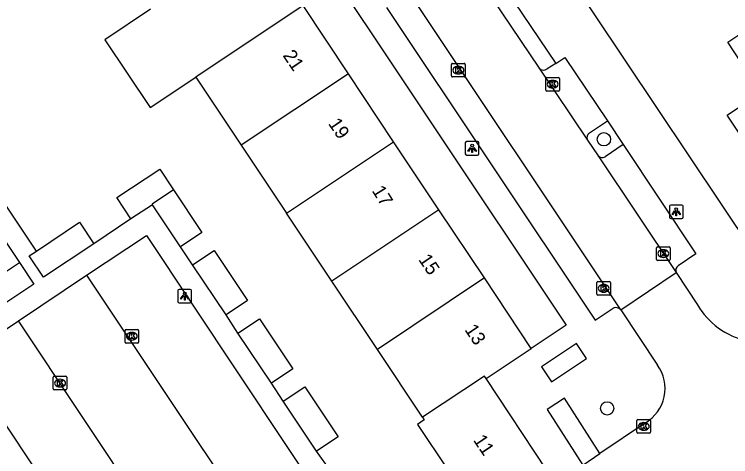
# Model space of a CAD drawing. Extents: x 158352 to 159489, y 383828 to 384597.
# Drawn here: x 158720.9 to 158773.4, y 384256.4 to 384288.8 of the extents above; entities that cross this region are included whole.
import ezdxf

# ---------------------------------------------------------------- set-up
doc = ezdxf.new("R2010")
doc.units = 0
for name, color, linetype in [('IMGEO_Boom', 7, 'Continuous'), ('IMGEO_Kolk', 7, 'Continuous'), ('IMGEO_Lichtpunt', 7, 'Continuous'), ('IMGEO_Pand', 7, 'Continuous'), ('IMGEO_Pand_nummerreeks', 7, 'Continuous'), ('IMGEO_Parkeervlak_open', 7, 'Continuous'), ('IMGEO_Rijbaan_lokaal_open', 7, 'Continuous'), ('IMGEO_Voetpad_open', 7, 'Continuous')]:
    doc.layers.add(name, color=color, linetype=linetype)

msp = doc.modelspace()

# ---------------------------------------------------------------- linework, layer by layer
at = {"layer": 'IMGEO_Boom'}
for centre in [(158764.134, 384279.661), (158764.374, 384259.935)]:
    msp.add_circle(centre, 0.489, dxfattribs=at)
at = {"layer": 'IMGEO_Kolk'}
for p, q in [((158752.962, 384284.303), (158752.962, 384285.155)), ((158753.037, 384285.229), (158753.889, 384285.229)), ((158753.45, 384285.009), (158753.475, 384285.009)), ((158753.963, 384285.155), (158753.963, 384284.303)), ((158753.889, 384284.229), (158753.037, 384284.229)), ((158753.473, 384284.449), (158753.448, 384284.449)), ((158759.875, 384283.273), (158759.875, 384284.125)), ((158759.95, 384284.199), (158760.802, 384284.199)), ((158760.363, 384283.979), (158760.388, 384283.979)), ((158760.876, 384284.125), (158760.876, 384283.273)), ((158760.802, 384283.199), (158759.95, 384283.199)), ((158760.386, 384283.419), (158760.361, 384283.419)), ((158767.994, 384270.857), (158767.994, 384271.709)), ((158768.069, 384271.783), (158768.921, 384271.783)), ((158768.482, 384271.563), (158768.507, 384271.563)), ((158768.995, 384271.709), (158768.995, 384270.857)), ((158768.505, 384271.003), (158768.48, 384271.003)), ((158768.921, 384270.783), (158768.069, 384270.783)), ((158763.617, 384268.308), (158763.617, 384269.16)), ((158763.692, 384269.234), (158764.544, 384269.234)), ((158764.105, 384269.014), (158764.13, 384269.014)), ((158764.618, 384269.16), (158764.618, 384268.308)), ((158764.544, 384268.234), (158763.692, 384268.234)), ((158764.128, 384268.454), (158764.103, 384268.454)), ((158729.011, 384264.798), (158729.011, 384265.65)), ((158729.086, 384265.724), (158729.938, 384265.724)), ((158730.012, 384265.65), (158730.012, 384264.798)), ((158729.499, 384265.504), (158729.524, 384265.504)), ((158729.938, 384264.724), (158729.086, 384264.724)), ((158729.522, 384264.944), (158729.497, 384264.944)), ((158723.749, 384261.361), (158723.749, 384262.213)), ((158723.824, 384262.287), (158724.676, 384262.287)), ((158724.237, 384262.067), (158724.262, 384262.067)), ((158724.75, 384262.213), (158724.75, 384261.361)), ((158724.26, 384261.507), (158724.235, 384261.507)), ((158724.676, 384261.287), (158723.824, 384261.287)), ((158766.558, 384258.189), (158766.558, 384259.041)), ((158766.633, 384259.115), (158767.485, 384259.115)), ((158767.046, 384258.895), (158767.071, 384258.895)), ((158767.559, 384259.041), (158767.559, 384258.189)), ((158767.069, 384258.335), (158767.044, 384258.335)), ((158767.485, 384258.115), (158766.633, 384258.115))]:
    msp.add_line(p, q, dxfattribs=at)
for points in [[(158752.962, 384284.303), (158752.962, 384285.155)], [(158753.037, 384285.229), (158753.889, 384285.229)], [(158753.963, 384285.155), (158753.963, 384284.303)], [(158753.283, 384284.929), (158753.406, 384284.929), (158753.406, 384284.778), (158753.536, 384284.929), (158753.7, 384284.929), (158753.554, 384284.778), (158753.707, 384284.529), (158753.555, 384284.529), (158753.47, 384284.693), (158753.406, 384284.626), (158753.406, 384284.529), (158753.283, 384284.529), (158753.283, 384284.929)], [(158753.889, 384284.229), (158753.037, 384284.229)], [(158759.875, 384283.273), (158759.875, 384284.125)], [(158759.95, 384284.199), (158760.802, 384284.199)], [(158760.876, 384284.125), (158760.876, 384283.273)], [(158760.196, 384283.899), (158760.319, 384283.899), (158760.319, 384283.748), (158760.449, 384283.899), (158760.613, 384283.899), (158760.467, 384283.748), (158760.62, 384283.499), (158760.468, 384283.499), (158760.383, 384283.663), (158760.319, 384283.596), (158760.319, 384283.499), (158760.196, 384283.499), (158760.196, 384283.899)], [(158760.802, 384283.199), (158759.95, 384283.199)], [(158767.994, 384270.857), (158767.994, 384271.709)], [(158768.069, 384271.783), (158768.921, 384271.783)], [(158768.315, 384271.483), (158768.438, 384271.483), (158768.438, 384271.332), (158768.568, 384271.483), (158768.732, 384271.483), (158768.586, 384271.332), (158768.739, 384271.083), (158768.587, 384271.083), (158768.502, 384271.247), (158768.438, 384271.18), (158768.438, 384271.083), (158768.315, 384271.083), (158768.315, 384271.483)], [(158768.995, 384271.709), (158768.995, 384270.857)], [(158768.921, 384270.783), (158768.069, 384270.783)], [(158763.617, 384268.308), (158763.617, 384269.16)], [(158763.692, 384269.234), (158764.544, 384269.234)], [(158763.938, 384268.934), (158764.061, 384268.934), (158764.061, 384268.783), (158764.191, 384268.934), (158764.355, 384268.934), (158764.209, 384268.783), (158764.362, 384268.534), (158764.21, 384268.534), (158764.125, 384268.698), (158764.061, 384268.631), (158764.061, 384268.534), (158763.938, 384268.534), (158763.938, 384268.934)], [(158764.618, 384269.16), (158764.618, 384268.308)], [(158764.544, 384268.234), (158763.692, 384268.234)], [(158729.011, 384264.798), (158729.011, 384265.65)], [(158729.086, 384265.724), (158729.938, 384265.724)], [(158730.012, 384265.65), (158730.012, 384264.798)], [(158729.332, 384265.424), (158729.455, 384265.424), (158729.455, 384265.273), (158729.585, 384265.424), (158729.749, 384265.424), (158729.603, 384265.273), (158729.756, 384265.024), (158729.604, 384265.024), (158729.519, 384265.188), (158729.455, 384265.121), (158729.455, 384265.024), (158729.332, 384265.024), (158729.332, 384265.424)], [(158729.938, 384264.724), (158729.086, 384264.724)], [(158723.749, 384261.361), (158723.749, 384262.213)], [(158723.824, 384262.287), (158724.676, 384262.287)], [(158724.07, 384261.987), (158724.193, 384261.987), (158724.193, 384261.836), (158724.323, 384261.987), (158724.487, 384261.987), (158724.341, 384261.836), (158724.494, 384261.587), (158724.342, 384261.587), (158724.257, 384261.751), (158724.193, 384261.684), (158724.193, 384261.587), (158724.07, 384261.587), (158724.07, 384261.987)], [(158724.75, 384262.213), (158724.75, 384261.361)], [(158724.676, 384261.287), (158723.824, 384261.287)], [(158766.558, 384258.189), (158766.558, 384259.041)], [(158766.633, 384259.115), (158767.485, 384259.115)], [(158766.879, 384258.815), (158767.002, 384258.815), (158767.002, 384258.664), (158767.132, 384258.815), (158767.296, 384258.815), (158767.15, 384258.664), (158767.303, 384258.415), (158767.151, 384258.415), (158767.066, 384258.579), (158767.002, 384258.512), (158767.002, 384258.415), (158766.879, 384258.415), (158766.879, 384258.815)], [(158767.559, 384259.041), (158767.559, 384258.189)], [(158767.485, 384258.115), (158766.633, 384258.115)]]:
    msp.add_lwpolyline(points, dxfattribs=at)
for centre, start, end in [((158753.039, 384285.153), 91.552, 178.448), ((158753.039, 384285.153), 91.552, 178.448), ((158753.887, 384285.153), 1.552, 88.448), ((158753.887, 384285.153), 1.552, 88.448), ((158753.039, 384284.305), 181.552, 268.448), ((158753.039, 384284.305), 181.552, 268.448), ((158753.887, 384284.305), 271.552, 358.448), ((158753.887, 384284.305), 271.552, 358.448), ((158759.952, 384284.123), 91.552, 178.448), ((158759.952, 384284.123), 91.552, 178.448), ((158760.8, 384284.123), 1.552, 88.448), ((158760.8, 384284.123), 1.552, 88.448), ((158759.952, 384283.275), 181.552, 268.448), ((158759.952, 384283.275), 181.552, 268.448), ((158760.8, 384283.275), 271.552, 358.448), ((158760.8, 384283.275), 271.552, 358.448), ((158768.071, 384271.707), 91.552, 178.448), ((158768.071, 384271.707), 91.552, 178.448), ((158768.919, 384271.707), 1.552, 88.448), ((158768.919, 384271.707), 1.552, 88.448), ((158768.071, 384270.859), 181.552, 268.448), ((158768.071, 384270.859), 181.552, 268.448), ((158768.919, 384270.859), 271.552, 358.448), ((158768.919, 384270.859), 271.552, 358.448), ((158763.694, 384269.158), 91.552, 178.448), ((158763.694, 384269.158), 91.552, 178.448), ((158764.542, 384269.158), 1.552, 88.448), ((158764.542, 384269.158), 1.552, 88.448), ((158763.694, 384268.31), 181.552, 268.448), ((158763.694, 384268.31), 181.552, 268.448), ((158764.542, 384268.31), 271.552, 358.448), ((158764.542, 384268.31), 271.552, 358.448), ((158729.088, 384265.648), 91.552, 178.448), ((158729.088, 384265.648), 91.552, 178.448), ((158729.936, 384265.648), 1.552, 88.448), ((158729.936, 384265.648), 1.552, 88.448), ((158729.088, 384264.8), 181.552, 268.448), ((158729.088, 384264.8), 181.552, 268.448), ((158729.936, 384264.8), 271.552, 358.448), ((158729.936, 384264.8), 271.552, 358.448), ((158723.826, 384262.211), 91.552, 178.448), ((158723.826, 384262.211), 91.552, 178.448), ((158724.674, 384262.211), 1.552, 88.448), ((158724.674, 384262.211), 1.552, 88.448), ((158723.826, 384261.363), 181.552, 268.448), ((158723.826, 384261.363), 181.552, 268.448), ((158724.674, 384261.363), 271.552, 358.448), ((158724.674, 384261.363), 271.552, 358.448), ((158766.635, 384259.039), 91.552, 178.448), ((158766.635, 384259.039), 91.552, 178.448), ((158767.483, 384259.039), 1.552, 88.448), ((158767.483, 384259.039), 1.552, 88.448), ((158766.635, 384258.191), 181.552, 268.448), ((158766.635, 384258.191), 181.552, 268.448), ((158767.483, 384258.191), 271.552, 358.448), ((158767.483, 384258.191), 271.552, 358.448)]:
    msp.add_arc(centre, 0.0765, start, end, dxfattribs=at)
for centre, major_axis, ratio, start_param, end_param in [((158753.449, 384284.729), (-0.387, 0.002), 0.722429, 4.712389, 7.853982), ((158753.474, 384284.729), (-0.39, 0.002), 0.717154, 1.570796, 4.712389), ((158760.362, 384283.699), (-0.387, 0.002), 0.722429, 4.712389, 7.853982), ((158760.387, 384283.699), (-0.39, 0.002), 0.717154, 1.570796, 4.712389), ((158768.481, 384271.283), (-0.387, 0.002), 0.722429, 4.712389, 7.853982), ((158768.506, 384271.283), (-0.39, 0.002), 0.717154, 1.570796, 4.712389), ((158764.104, 384268.734), (-0.387, 0.002), 0.722429, 4.712389, 7.853982), ((158764.129, 384268.734), (-0.39, 0.002), 0.717154, 1.570796, 4.712389), ((158729.498, 384265.224), (-0.387, 0.002), 0.722429, 4.712389, 7.853982), ((158729.523, 384265.224), (-0.39, 0.002), 0.717154, 1.570796, 4.712389), ((158724.236, 384261.787), (-0.387, 0.002), 0.722429, 4.712389, 7.853982), ((158724.261, 384261.787), (-0.39, 0.002), 0.717154, 1.570796, 4.712389), ((158767.045, 384258.615), (-0.387, 0.002), 0.722429, 4.712389, 7.853982), ((158767.07, 384258.615), (-0.39, 0.002), 0.717154, 1.570796, 4.712389)]:
    msp.add_ellipse(centre, major_axis=major_axis, ratio=ratio, start_param=start_param, end_param=end_param, dxfattribs=at)
at = {"layer": 'IMGEO_Lichtpunt'}
for p, q in [((158753.97, 384279.399), (158753.97, 384278.592)), ((158753.97, 384279.399), (158753.97, 384278.592)), ((158754.872, 384279.494), (158754.064, 384279.494)), ((158754.872, 384279.494), (158754.064, 384279.494)), ((158754.966, 384278.592), (158754.966, 384279.399)), ((158754.966, 384278.592), (158754.966, 384279.399)), ((158754.064, 384278.498), (158754.872, 384278.498)), ((158754.064, 384278.498), (158754.872, 384278.498)), ((158768.947, 384274.748), (158768.947, 384273.941)), ((158768.947, 384274.748), (158768.947, 384273.941)), ((158769.849, 384274.843), (158769.041, 384274.843)), ((158769.849, 384274.843), (158769.041, 384274.843)), ((158769.943, 384273.941), (158769.943, 384274.748)), ((158769.943, 384273.941), (158769.943, 384274.748)), ((158769.041, 384273.847), (158769.849, 384273.847)), ((158769.041, 384273.847), (158769.849, 384273.847)), ((158732.891, 384268.566), (158732.891, 384267.759)), ((158732.891, 384268.566), (158732.891, 384267.759)), ((158733.793, 384268.661), (158732.985, 384268.661)), ((158733.793, 384268.661), (158732.985, 384268.661)), ((158733.887, 384267.759), (158733.887, 384268.566)), ((158733.887, 384267.759), (158733.887, 384268.566)), ((158732.985, 384267.665), (158733.793, 384267.665)), ((158732.985, 384267.665), (158733.793, 384267.665))]:
    msp.add_line(p, q, dxfattribs=at)
for points in [[(158754.344, 384279.063), (158754.383, 384279.035), (158754.195, 384278.773), (158754.157, 384278.8), (158754.344, 384279.063)], [(158754.446, 384279.015), (158754.493, 384279.015), (158754.493, 384278.693), (158754.446, 384278.693), (158754.446, 384279.015)], [(158754.556, 384279.035), (158754.594, 384279.062), (158754.781, 384278.8), (158754.742, 384278.772), (158754.556, 384279.035)], [(158769.321, 384274.412), (158769.36, 384274.384), (158769.172, 384274.122), (158769.134, 384274.149), (158769.321, 384274.412)], [(158769.423, 384274.364), (158769.47, 384274.364), (158769.47, 384274.042), (158769.423, 384274.042), (158769.423, 384274.364)], [(158769.533, 384274.384), (158769.571, 384274.411), (158769.758, 384274.149), (158769.719, 384274.121), (158769.533, 384274.384)], [(158733.265, 384268.23), (158733.304, 384268.202), (158733.116, 384267.94), (158733.078, 384267.967), (158733.265, 384268.23)], [(158733.477, 384268.202), (158733.515, 384268.229), (158733.702, 384267.967), (158733.663, 384267.939), (158733.477, 384268.202)], [(158733.367, 384268.182), (158733.414, 384268.182), (158733.414, 384267.86), (158733.367, 384267.86), (158733.367, 384268.182)]]:
    msp.add_lwpolyline(points, dxfattribs=at)
for centre in [(158754.469, 384279.197), (158769.446, 384274.546), (158733.39, 384268.364)]:
    msp.add_circle(centre, 0.0994, dxfattribs=at)
for centre, start, end in [((158754.064, 384279.399), 90, 180), ((158754.064, 384279.399), 90, 180), ((158754.872, 384279.399), 0, 90), ((158754.872, 384279.399), 0, 90), ((158754.064, 384278.592), 180, 270), ((158754.064, 384278.592), 180, 270), ((158754.872, 384278.592), 270, 0), ((158754.872, 384278.592), 270, 360), ((158769.041, 384274.748), 90, 180), ((158769.041, 384274.748), 90, 180), ((158769.849, 384274.748), 0, 90), ((158769.849, 384274.748), 0, 90), ((158769.041, 384273.941), 180, 270), ((158769.041, 384273.941), 180, 270), ((158769.849, 384273.941), 270, 0), ((158769.849, 384273.941), 270, 360), ((158732.985, 384268.566), 90, 180), ((158732.985, 384268.566), 90, 180), ((158733.793, 384268.566), 0, 90), ((158733.793, 384268.566), 0, 90), ((158732.985, 384267.759), 180, 270), ((158732.985, 384267.759), 180, 270), ((158733.793, 384267.759), 270, 0), ((158733.793, 384267.759), 270, 360)]:
    msp.add_arc(centre, 0.0946, start, end, dxfattribs=at)
at = {"layer": 'IMGEO_Pand'}
for points in [[(158742.072, 384289.458), (158734.206, 384284.214)], [(158745.403, 384284.464), (158742.072, 384289.458)], [(158730.885, 384289.193), (158727.536, 384286.959), (158730.857, 384281.98), (158734.206, 384284.214)], [(158782.778, 384277.92), (158782.485, 384277.724), (158781.598, 384277.131), (158777.776, 384274.575), (158773.184, 384281.419), (158775.655, 384283.088), (158773.226, 384286.774), (158775.712, 384288.452)], [(158734.206, 384284.214), (158737.537, 384279.22)], [(158745.403, 384284.464), (158737.537, 384279.22)], [(158748.711, 384279.476), (158745.403, 384284.464)], [(158740.858, 384274.242), (158748.711, 384279.476)], [(158752.04, 384274.482), (158748.711, 384279.476)], [(158737.537, 384279.22), (158740.858, 384274.242)], [(158729.445, 384273.825), (158728.408, 384275.388), (158731.566, 384277.483), (158732.573, 384275.966)], [(158732.573, 384275.966), (158730.995, 384274.914), (158731.036, 384274.853)], [(158732.573, 384275.966), (158734.658, 384272.824), (158733.089, 384271.777)], [(158731.036, 384274.853), (158729.445, 384273.825)], [(158733.089, 384271.777), (158731.036, 384274.853)], [(158744.188, 384269.248), (158740.858, 384274.242)], [(158752.04, 384274.482), (158744.188, 384269.248)], [(158755.386, 384269.499), (158752.04, 384274.482)], [(158722.518, 384271.47), (158725.675, 384273.583), (158726.727, 384272.009)], [(158726.727, 384272.009), (158723.043, 384269.549), (158721.994, 384271.119), (158722.518, 384271.47)], [(158733.969, 384270.457), (158735.549, 384271.513), (158738.004, 384267.841), (158736.425, 384266.785)], [(158719.157, 384266.937), (158718.102, 384268.516), (158721.266, 384270.631)], [(158721.266, 384270.631), (158722.322, 384269.051), (158719.157, 384266.937)], [(158736.425, 384266.785), (158733.969, 384270.457)], [(158747.519, 384264.255), (158744.188, 384269.248)], [(158755.386, 384269.499), (158747.519, 384264.255)], [(158758.812, 384264.322), (158755.386, 384269.499)], [(158737.288, 384265.443), (158738.865, 384266.503), (158741.323, 384262.843), (158739.746, 384261.784)], [(158739.746, 384261.784), (158737.288, 384265.443)], [(158750.839, 384259.277), (158747.519, 384264.255)], [(158755.506, 384262.112), (158758.812, 384264.322)], [(158755.506, 384262.112), (158755.377, 384262.305), (158750.839, 384259.277)], [(158759.926, 384255.435), (158755.506, 384262.112)], [(158740.612, 384260.46), (158742.19, 384261.517), (158744.646, 384257.849), (158743.067, 384256.792)], [(158743.067, 384256.792), (158740.612, 384260.46)], [(158750.839, 384259.277), (158750.964, 384259.082), (158750.465, 384258.749), (158754.903, 384252.103)]]:
    msp.add_lwpolyline(points, dxfattribs=at)
at = {"layer": 'IMGEO_Parkeervlak_open'}
for points in [[(158763.077, 384280.128), (158764.388, 384281.013)], [(158765.546, 384279.273), (158764.225, 384278.38)]]:
    msp.add_lwpolyline(points, dxfattribs=at)
for centre, radius, start, end in [((158763.318, 384279.765), 0.436, 123.5537, 204.3884), ((158764.021, 384278.79), 0.458, 226.2326, 296.5231)]:
    msp.add_arc(centre, radius, start, end, dxfattribs=at)
at = {"layer": 'IMGEO_Rijbaan_lokaal_open'}
for points in [[(158765.371, 384267.168), (158749.656, 384290.73)], [(158755.951, 384290.012), (158759.379, 384284.871)], [(158759.379, 384284.871), (158762.921, 384279.585)], [(158762.921, 384279.585), (158763.704, 384278.459)], [(158763.704, 384278.459), (158769.43, 384269.883)], [(158765.371, 384267.168), (158769.43, 384269.883)], [(158769.43, 384269.883), (158770.993, 384267.518)], [(158721.205, 384266.361), (158726.176, 384269.689)], [(158726.176, 384269.689), (158743.37, 384243.965)], [(158765.371, 384267.168), (158768.069, 384263.097)], [(158735.025, 384245.603), (158721.205, 384266.361)], [(158767.178, 384258.876), (158763.847, 384256.62)], [(158762.589, 384255.767), (158763.847, 384256.62)]]:
    msp.add_lwpolyline(points, dxfattribs=at)
for centre, radius, start, end in [((158775.899, 384270.46), 5.72, 210.9501, 302.7135), ((158765.716, 384261.389), 2.907, 300.1819, 35.9793)]:
    msp.add_arc(centre, radius, start, end, dxfattribs=at)
at = {"layer": 'IMGEO_Voetpad_open'}
for points in [[(158721.854, 384325.255), (158761.364, 384266.025), (158758.812, 384264.322)], [(158777.399, 384267.966), (158761.047, 384292.415), (158760.941, 384292.573)], [(158755.951, 384290.012), (158756.941, 384290.664), (158760.598, 384285.21)], [(158748.187, 384289.313), (158763.493, 384266.393), (158764.827, 384267.282)], [(158760.598, 384285.21), (158761.282, 384285.648), (158764.388, 384281.013)], [(158760.598, 384285.21), (158759.986, 384284.817)], [(158722.518, 384271.47), (158718.072, 384278.112), (158715.949, 384281.294)], [(158764.388, 384281.013), (158765.546, 384279.273)], [(158765.546, 384279.273), (158770.88, 384271.274), (158769.576, 384270.391)], [(158716.773, 384277.343), (158721.266, 384270.631)], [(158729.445, 384273.825), (158726.727, 384272.009)], [(158726.176, 384269.689), (158730.582, 384272.613), (158747.486, 384247.227), (158743.506, 384244.605)], [(158733.969, 384270.457), (158733.089, 384271.777)], [(158737.288, 384265.443), (158736.425, 384266.785)], [(158734.381, 384245.705), (158730.524, 384243.314), (158717.046, 384263.571), (158721.205, 384266.361)], [(158759.568, 384262.991), (158760.3, 384261.887), (158762.862, 384263.586), (158762.13, 384264.69), (158759.568, 384262.991)], [(158740.612, 384260.46), (158739.746, 384261.784)], [(158763.847, 384256.62), (158761.247, 384260.675), (158759.968, 384259.855), (158762.589, 384255.767)], [(158744.096, 384255.329), (158743.067, 384256.792)]]:
    msp.add_lwpolyline(points, dxfattribs=at)
for centre, radius, start, end in [((158759.715, 384285.212), 0.479, 225.4112, 304.4213), ((158769.826, 384270.044), 0.427, 125.7784, 202.1521), ((158765.023, 384266.864), 0.462, 41.1735, 115.1554)]:
    msp.add_arc(centre, radius, start, end, dxfattribs=at)

# ---------------------------------------------------------------- texts
at = {"layer": 'IMGEO_Pand_nummerreeks'}
for s, rotation, p in [('21', 304.143, (158740.549, 384285.804)), ('19', 304.0804, (158743.883, 384280.809)), ('17', 302.0492, (158747.087, 384275.897)), ('15', 304.2072, (158750.497, 384270.841)), ('13', 304.0804, (158753.882, 384265.702)), ('11', 303.909, (158754.515, 384257.608))]:
    msp.add_text(s, height=1, rotation=rotation, dxfattribs=at).set_placement(p)

doc.saveas('drawing.dxf')
